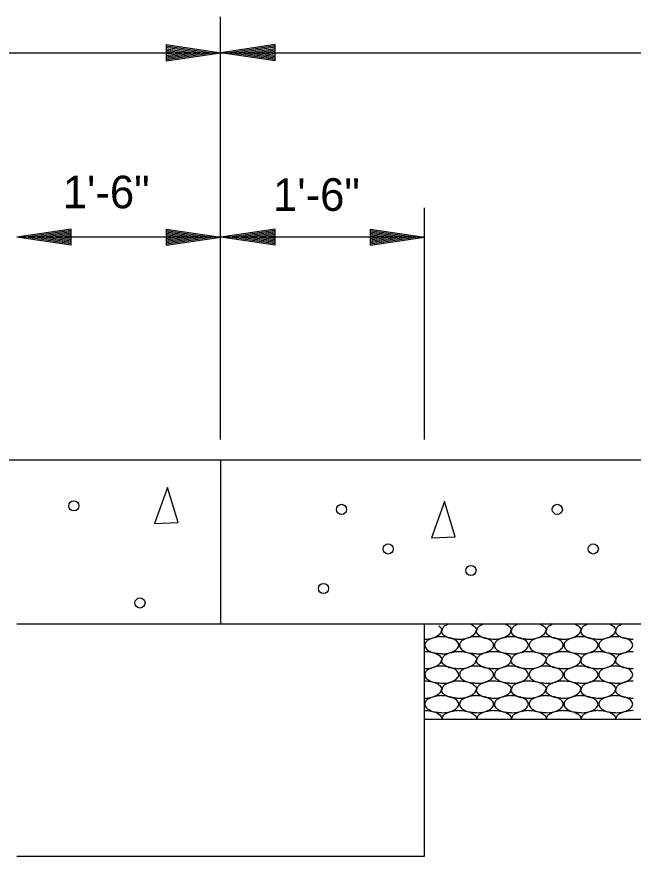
# Model space of a CAD drawing. Extents: x 3287 to 1767681, y -265 to 581440.
# Drawn here: x 3441.9 to 3464.58, y -239.71 to -208.81 of the extents above; entities that cross this region are included whole.
import ezdxf

# ---------------------------------------------------------------- set-up
doc = ezdxf.new("R2010")
doc.units = 0
doc.layers.add('Default', color=7, linetype='Continuous')

msp = doc.modelspace()

# ---------------------------------------------------------------- linework, layer by layer
at = {"layer": 'Default'}
for p, q in [((3449.399, -224.366), (3449.399, -208.806)), ((3447.401, -209.83), (3449.401, -210.13)), ((3447.401, -209.83), (3447.401, -210.43)), ((3447.401, -209.88), (3449.066, -210.13)), ((3447.401, -209.93), (3448.721, -210.13)), ((3447.401, -209.98), (3448.391, -210.13)), ((3447.401, -210.03), (3448.051, -210.13)), ((3447.401, -210.08), (3447.716, -210.13)), ((3451.401, -209.83), (3449.401, -210.13)), ((3451.401, -209.88), (3449.736, -210.13)), ((3451.401, -209.93), (3450.076, -210.13)), ((3451.401, -209.98), (3450.411, -210.13)), ((3451.401, -210.03), (3450.751, -210.13)), ((3451.401, -210.08), (3451.086, -210.13)), ((3451.401, -210.43), (3451.401, -209.83)), ((3349.405, -210.128), (3449.399, -210.128)), ((3447.401, -210.43), (3449.401, -210.13)), ((3447.401, -210.225), (3448.051, -210.13)), ((3447.401, -210.33), (3448.721, -210.13)), ((3447.401, -210.38), (3449.066, -210.13)), ((3447.401, -210.28), (3448.391, -210.13)), ((3447.401, -210.175), (3447.716, -210.13)), ((3449.399, -210.128), (3531.893, -210.128)), ((3451.401, -210.43), (3449.401, -210.13)), ((3451.401, -210.38), (3449.736, -210.13)), ((3451.401, -210.33), (3450.076, -210.13)), ((3451.401, -210.28), (3450.411, -210.13)), ((3451.401, -210.225), (3450.751, -210.13)), ((3451.401, -210.175), (3451.086, -210.13)), ((3456.898, -224.366), (3456.898, -215.841)), ((3449.399, -216.918), (3441.899, -216.918)), ((3443.902, -216.619), (3441.902, -216.919)), ((3443.902, -217.219), (3441.902, -216.919)), ((3443.902, -216.669), (3442.237, -216.919)), ((3443.902, -217.169), (3442.237, -216.919)), ((3443.902, -216.719), (3442.577, -216.919)), ((3443.902, -217.119), (3442.577, -216.919)), ((3443.902, -216.769), (3442.912, -216.919)), ((3443.902, -217.069), (3442.912, -216.919)), ((3443.902, -216.819), (3443.252, -216.919)), ((3443.902, -217.014), (3443.252, -216.919)), ((3443.902, -216.869), (3443.587, -216.919)), ((3443.902, -216.964), (3443.587, -216.919)), ((3443.902, -217.219), (3443.902, -216.619)), ((3447.401, -216.619), (3449.401, -216.919)), ((3447.401, -216.619), (3447.401, -217.219)), ((3447.401, -216.669), (3449.066, -216.919)), ((3447.401, -216.719), (3448.721, -216.919)), ((3447.401, -216.769), (3448.391, -216.919)), ((3447.401, -216.819), (3448.051, -216.919)), ((3447.401, -216.869), (3447.716, -216.919)), ((3447.401, -217.219), (3449.401, -216.919)), ((3447.401, -217.014), (3448.051, -216.919)), ((3447.401, -217.119), (3448.721, -216.919)), ((3447.401, -217.169), (3449.066, -216.919)), ((3447.401, -217.069), (3448.391, -216.919)), ((3447.401, -216.964), (3447.716, -216.919)), ((3456.898, -216.918), (3449.399, -216.918)), ((3451.401, -216.619), (3449.401, -216.919)), ((3451.401, -217.219), (3449.401, -216.919)), ((3451.401, -216.669), (3449.736, -216.919)), ((3451.401, -217.169), (3449.736, -216.919)), ((3451.401, -216.719), (3450.076, -216.919)), ((3451.401, -217.119), (3450.076, -216.919)), ((3451.401, -216.769), (3450.411, -216.919)), ((3451.401, -217.069), (3450.411, -216.919)), ((3451.401, -216.819), (3450.751, -216.919)), ((3451.401, -217.014), (3450.751, -216.919)), ((3451.401, -216.869), (3451.086, -216.919)), ((3451.401, -216.964), (3451.086, -216.919)), ((3451.401, -217.219), (3451.401, -216.619)), ((3454.901, -216.619), (3456.901, -216.919)), ((3454.901, -216.619), (3454.901, -217.219)), ((3454.901, -216.669), (3456.566, -216.919)), ((3454.901, -216.719), (3456.221, -216.919)), ((3454.901, -216.769), (3455.891, -216.919)), ((3454.901, -216.819), (3455.551, -216.919)), ((3454.901, -216.869), (3455.216, -216.919)), ((3454.901, -217.219), (3456.901, -216.919)), ((3454.901, -217.014), (3455.551, -216.919)), ((3454.901, -217.119), (3456.221, -216.919)), ((3454.901, -217.169), (3456.566, -216.919)), ((3454.901, -217.069), (3455.891, -216.919)), ((3454.901, -216.964), (3455.216, -216.919)), ((3349.405, -225.116), (3531.893, -225.116)), ((3449.399, -225.116), (3449.399, -231.157)), ((3441.899, -231.157), (3456.898, -231.157)), ((3456.898, -239.707), (3456.898, -231.157)), ((3456.898, -231.157), (3524.394, -231.157)), ((3456.898, -232.167), (3456.913, -232.167)), ((3458.178, -232.167), (3458.193, -232.167)), ((3459.458, -232.167), (3459.473, -232.167)), ((3460.738, -232.167), (3460.753, -232.167)), ((3462.018, -232.167), (3462.033, -232.167)), ((3463.298, -232.167), (3463.313, -232.167)), ((3456.898, -233.252), (3456.913, -233.252)), ((3458.178, -233.252), (3458.193, -233.252)), ((3459.458, -233.252), (3459.473, -233.252)), ((3460.738, -233.252), (3460.753, -233.252)), ((3462.018, -233.252), (3462.033, -233.252)), ((3463.298, -233.252), (3463.313, -233.252)), ((3456.898, -234.337), (3456.913, -234.337)), ((3458.178, -234.337), (3458.193, -234.337)), ((3459.458, -234.337), (3459.473, -234.337)), ((3460.738, -234.337), (3460.753, -234.337)), ((3462.018, -234.337), (3462.033, -234.337)), ((3463.298, -234.337), (3463.313, -234.337)), ((3456.898, -234.657), (3516.894, -234.657)), ((3441.899, -239.707), (3456.898, -239.707))]:
    msp.add_line(p, q, dxfattribs=at)
for points in [[(3447.446, -226.129), (3446.961, -227.454), (3447.841, -227.419), (3447.446, -226.129)], [(3457.636, -226.654), (3457.151, -227.984), (3458.031, -227.949), (3457.636, -226.654)]]:
    msp.add_lwpolyline(points, dxfattribs=at)
for centre in [(3443.998, -226.807), (3453.844, -226.94), (3461.785, -226.94), (3455.564, -228.396), (3463.109, -228.396), (3458.609, -229.191), (3453.182, -229.853), (3446.432, -230.383)]:
    msp.add_circle(centre, 0.187, dxfattribs=at)
for points in [[(3457.508, -231.402), (3457.508, -231.417), (3457.438, -231.552), (3457.363, -231.612), (3457.208, -231.682), (3456.993, -231.727), (3456.928, -231.728)], [(3457.432, -231.225), (3457.518, -231.322), (3457.538, -231.397), (3457.538, -231.402)], [(3457.728, -231.157), (3457.648, -231.167), (3457.538, -231.167), (3457.492, -231.164)], [(3458.178, -231.727), (3458.158, -231.727), (3457.993, -231.712), (3457.813, -231.682), (3457.678, -231.617), (3457.553, -231.502), (3457.533, -231.417), (3457.533, -231.402)], [(3457.553, -231.402), (3457.553, -231.397), (3457.593, -231.277), (3457.693, -231.197), (3457.779, -231.157)], [(3458.788, -231.402), (3458.788, -231.417), (3458.718, -231.552), (3458.643, -231.612), (3458.488, -231.682), (3458.273, -231.727), (3458.178, -231.727)], [(3458.582, -231.157), (3458.668, -231.197), (3458.798, -231.322), (3458.818, -231.397), (3458.818, -231.402)], [(3459.008, -231.157), (3458.928, -231.167), (3458.818, -231.167), (3458.7, -231.157)], [(3459.458, -231.727), (3459.438, -231.727), (3459.273, -231.712), (3459.093, -231.682), (3458.958, -231.617), (3458.833, -231.502), (3458.813, -231.417), (3458.813, -231.402)], [(3458.833, -231.402), (3458.833, -231.397), (3458.873, -231.277), (3458.973, -231.197), (3459.059, -231.157)], [(3460.068, -231.402), (3460.068, -231.417), (3459.998, -231.552), (3459.923, -231.612), (3459.768, -231.682), (3459.553, -231.727), (3459.458, -231.727)], [(3459.862, -231.157), (3459.948, -231.197), (3460.078, -231.322), (3460.098, -231.397), (3460.098, -231.402)], [(3460.287, -231.157), (3460.208, -231.167), (3460.098, -231.167), (3459.98, -231.157)], [(3460.738, -231.727), (3460.718, -231.727), (3460.553, -231.712), (3460.373, -231.682), (3460.238, -231.617), (3460.113, -231.502), (3460.093, -231.417), (3460.093, -231.402)], [(3460.113, -231.402), (3460.113, -231.397), (3460.153, -231.277), (3460.253, -231.197), (3460.339, -231.157)], [(3461.348, -231.402), (3461.348, -231.417), (3461.278, -231.552), (3461.203, -231.612), (3461.048, -231.682), (3460.833, -231.727), (3460.738, -231.727)], [(3461.142, -231.157), (3461.228, -231.197), (3461.358, -231.322), (3461.378, -231.397), (3461.378, -231.402)], [(3461.567, -231.157), (3461.488, -231.167), (3461.378, -231.167), (3461.26, -231.157)], [(3462.018, -231.727), (3461.998, -231.727), (3461.833, -231.712), (3461.653, -231.682), (3461.518, -231.617), (3461.393, -231.502), (3461.373, -231.417), (3461.373, -231.402)], [(3461.393, -231.402), (3461.393, -231.397), (3461.433, -231.277), (3461.533, -231.197), (3461.619, -231.157)], [(3462.628, -231.402), (3462.628, -231.417), (3462.558, -231.552), (3462.483, -231.612), (3462.328, -231.682), (3462.113, -231.727), (3462.018, -231.727)], [(3462.422, -231.157), (3462.508, -231.197), (3462.638, -231.322), (3462.658, -231.397), (3462.658, -231.402)], [(3462.847, -231.157), (3462.768, -231.167), (3462.658, -231.167), (3462.54, -231.157)], [(3463.298, -231.727), (3463.278, -231.727), (3463.113, -231.712), (3462.933, -231.682), (3462.798, -231.617), (3462.673, -231.502), (3462.653, -231.417), (3462.653, -231.402)], [(3462.673, -231.402), (3462.673, -231.397), (3462.713, -231.277), (3462.813, -231.197), (3462.899, -231.157)], [(3463.908, -231.402), (3463.908, -231.417), (3463.838, -231.552), (3463.763, -231.612), (3463.608, -231.682), (3463.393, -231.727), (3463.298, -231.727)], [(3463.702, -231.157), (3463.788, -231.197), (3463.918, -231.322), (3463.938, -231.397), (3463.938, -231.402)], [(3464.127, -231.157), (3464.048, -231.167), (3463.938, -231.167), (3463.82, -231.157)], [(3464.578, -231.727), (3464.558, -231.727), (3464.393, -231.712), (3464.213, -231.682), (3464.078, -231.617), (3463.953, -231.502), (3463.933, -231.417), (3463.933, -231.402)], [(3463.953, -231.402), (3463.953, -231.397), (3463.993, -231.277), (3464.093, -231.197), (3464.179, -231.157)], [(3457.538, -231.627), (3457.758, -231.652), (3458.013, -231.742), (3458.143, -231.867), (3458.163, -231.942), (3458.093, -232.077), (3458.018, -232.137), (3457.863, -232.207), (3457.648, -232.252), (3457.538, -232.252), (3457.373, -232.237), (3457.193, -232.207), (3457.058, -232.142), (3456.933, -232.027), (3456.913, -231.942), (3456.953, -231.822), (3457.053, -231.742), (3457.153, -231.697), (3457.303, -231.652), (3457.398, -231.632), (3457.538, -231.627)], [(3458.818, -231.627), (3459.038, -231.652), (3459.293, -231.742), (3459.423, -231.867), (3459.443, -231.942), (3459.373, -232.077), (3459.298, -232.137), (3459.143, -232.207), (3458.928, -232.252), (3458.818, -232.252), (3458.653, -232.237), (3458.473, -232.207), (3458.338, -232.142), (3458.213, -232.027), (3458.193, -231.942), (3458.233, -231.822), (3458.333, -231.742), (3458.433, -231.697), (3458.583, -231.652), (3458.678, -231.632), (3458.818, -231.627)], [(3460.098, -231.627), (3460.318, -231.652), (3460.573, -231.742), (3460.703, -231.867), (3460.723, -231.942), (3460.653, -232.077), (3460.578, -232.137), (3460.423, -232.207), (3460.208, -232.252), (3460.098, -232.252), (3459.933, -232.237), (3459.753, -232.207), (3459.618, -232.142), (3459.493, -232.027), (3459.473, -231.942), (3459.513, -231.822), (3459.613, -231.742), (3459.713, -231.697), (3459.863, -231.652), (3459.958, -231.632), (3460.098, -231.627)], [(3461.378, -231.627), (3461.598, -231.652), (3461.853, -231.742), (3461.983, -231.867), (3462.003, -231.942), (3461.933, -232.077), (3461.858, -232.137), (3461.703, -232.207), (3461.488, -232.252), (3461.378, -232.252), (3461.213, -232.237), (3461.033, -232.207), (3460.898, -232.142), (3460.773, -232.027), (3460.753, -231.942), (3460.793, -231.822), (3460.893, -231.742), (3460.993, -231.697), (3461.143, -231.652), (3461.238, -231.632), (3461.378, -231.627)], [(3462.658, -231.627), (3462.878, -231.652), (3463.133, -231.742), (3463.263, -231.867), (3463.283, -231.942), (3463.213, -232.077), (3463.138, -232.137), (3462.983, -232.207), (3462.768, -232.252), (3462.658, -232.252), (3462.493, -232.237), (3462.313, -232.207), (3462.178, -232.142), (3462.053, -232.027), (3462.033, -231.942), (3462.073, -231.822), (3462.173, -231.742), (3462.273, -231.697), (3462.423, -231.652), (3462.518, -231.632), (3462.658, -231.627)], [(3463.938, -231.627), (3464.158, -231.652), (3464.413, -231.742), (3464.543, -231.867), (3464.563, -231.942), (3464.493, -232.077), (3464.418, -232.137), (3464.263, -232.207), (3464.048, -232.252), (3463.938, -232.252), (3463.773, -232.237), (3463.593, -232.207), (3463.458, -232.142), (3463.333, -232.027), (3463.313, -231.942), (3463.353, -231.822), (3463.453, -231.742), (3463.553, -231.697), (3463.703, -231.652), (3463.798, -231.632), (3463.938, -231.627)], [(3456.913, -232.167), (3457.133, -232.192), (3457.388, -232.282), (3457.518, -232.407), (3457.538, -232.482), (3457.538, -232.487)], [(3457.553, -232.487), (3457.553, -232.482), (3457.593, -232.362), (3457.693, -232.282), (3457.793, -232.237), (3457.943, -232.192), (3458.038, -232.172), (3458.178, -232.167)], [(3458.193, -232.167), (3458.413, -232.192), (3458.668, -232.282), (3458.798, -232.407), (3458.818, -232.482), (3458.818, -232.487)], [(3458.833, -232.487), (3458.833, -232.482), (3458.873, -232.362), (3458.973, -232.282), (3459.073, -232.237), (3459.223, -232.192), (3459.318, -232.172), (3459.458, -232.167)], [(3459.473, -232.167), (3459.693, -232.192), (3459.948, -232.282), (3460.078, -232.407), (3460.098, -232.482), (3460.098, -232.487)], [(3460.113, -232.487), (3460.113, -232.482), (3460.153, -232.362), (3460.253, -232.282), (3460.353, -232.237), (3460.503, -232.192), (3460.598, -232.172), (3460.738, -232.167)], [(3460.753, -232.167), (3460.973, -232.192), (3461.228, -232.282), (3461.358, -232.407), (3461.378, -232.482), (3461.378, -232.487)], [(3461.393, -232.487), (3461.393, -232.482), (3461.433, -232.362), (3461.533, -232.282), (3461.633, -232.237), (3461.783, -232.192), (3461.878, -232.172), (3462.018, -232.167)], [(3462.033, -232.167), (3462.253, -232.192), (3462.508, -232.282), (3462.638, -232.407), (3462.658, -232.482), (3462.658, -232.487)], [(3462.673, -232.487), (3462.673, -232.482), (3462.713, -232.362), (3462.813, -232.282), (3462.913, -232.237), (3463.063, -232.192), (3463.158, -232.172), (3463.298, -232.167)], [(3463.313, -232.167), (3463.533, -232.192), (3463.788, -232.282), (3463.918, -232.407), (3463.938, -232.482), (3463.938, -232.487)], [(3463.953, -232.487), (3463.953, -232.482), (3463.993, -232.362), (3464.093, -232.282), (3464.193, -232.237), (3464.343, -232.192), (3464.438, -232.172), (3464.578, -232.167)], [(3457.508, -232.487), (3457.508, -232.502), (3457.438, -232.637), (3457.363, -232.697), (3457.208, -232.767), (3456.993, -232.812), (3456.898, -232.812)], [(3458.178, -232.812), (3458.158, -232.812), (3457.993, -232.797), (3457.813, -232.767), (3457.678, -232.702), (3457.553, -232.587), (3457.533, -232.502), (3457.533, -232.487)], [(3458.788, -232.487), (3458.788, -232.502), (3458.718, -232.637), (3458.643, -232.697), (3458.488, -232.767), (3458.273, -232.812), (3458.178, -232.812)], [(3459.458, -232.812), (3459.438, -232.812), (3459.273, -232.797), (3459.093, -232.767), (3458.958, -232.702), (3458.833, -232.587), (3458.813, -232.502), (3458.813, -232.487)], [(3460.068, -232.487), (3460.068, -232.502), (3459.998, -232.637), (3459.923, -232.697), (3459.768, -232.767), (3459.553, -232.812), (3459.458, -232.812)], [(3460.738, -232.812), (3460.718, -232.812), (3460.553, -232.797), (3460.373, -232.767), (3460.238, -232.702), (3460.113, -232.587), (3460.093, -232.502), (3460.093, -232.487)], [(3461.348, -232.487), (3461.348, -232.502), (3461.278, -232.637), (3461.203, -232.697), (3461.048, -232.767), (3460.833, -232.812), (3460.738, -232.812)], [(3462.018, -232.812), (3461.998, -232.812), (3461.833, -232.797), (3461.653, -232.767), (3461.518, -232.702), (3461.393, -232.587), (3461.373, -232.502), (3461.373, -232.487)], [(3462.628, -232.487), (3462.628, -232.502), (3462.558, -232.637), (3462.483, -232.697), (3462.328, -232.767), (3462.113, -232.812), (3462.018, -232.812)], [(3463.298, -232.812), (3463.278, -232.812), (3463.113, -232.797), (3462.933, -232.767), (3462.798, -232.702), (3462.673, -232.587), (3462.653, -232.502), (3462.653, -232.487)], [(3463.908, -232.487), (3463.908, -232.502), (3463.838, -232.637), (3463.763, -232.697), (3463.608, -232.767), (3463.393, -232.812), (3463.298, -232.812)], [(3464.578, -232.812), (3464.558, -232.812), (3464.393, -232.797), (3464.213, -232.767), (3464.078, -232.702), (3463.953, -232.587), (3463.933, -232.502), (3463.933, -232.487)], [(3457.538, -232.712), (3457.758, -232.737), (3458.013, -232.827), (3458.143, -232.952), (3458.163, -233.027), (3458.093, -233.162), (3458.018, -233.222), (3457.863, -233.292), (3457.648, -233.337), (3457.538, -233.337), (3457.373, -233.322), (3457.193, -233.292), (3457.058, -233.227), (3456.933, -233.112), (3456.913, -233.027), (3456.953, -232.907), (3457.053, -232.827), (3457.153, -232.782), (3457.303, -232.737), (3457.398, -232.717), (3457.538, -232.712)], [(3458.818, -232.712), (3459.038, -232.737), (3459.293, -232.827), (3459.423, -232.952), (3459.443, -233.027), (3459.373, -233.162), (3459.298, -233.222), (3459.143, -233.292), (3458.928, -233.337), (3458.818, -233.337), (3458.653, -233.322), (3458.473, -233.292), (3458.338, -233.227), (3458.213, -233.112), (3458.193, -233.027), (3458.233, -232.907), (3458.333, -232.827), (3458.433, -232.782), (3458.583, -232.737), (3458.678, -232.717), (3458.818, -232.712)], [(3460.098, -232.712), (3460.318, -232.737), (3460.573, -232.827), (3460.703, -232.952), (3460.723, -233.027), (3460.653, -233.162), (3460.578, -233.222), (3460.423, -233.292), (3460.208, -233.337), (3460.098, -233.337), (3459.933, -233.322), (3459.753, -233.292), (3459.618, -233.227), (3459.493, -233.112), (3459.473, -233.027), (3459.513, -232.907), (3459.613, -232.827), (3459.713, -232.782), (3459.863, -232.737), (3459.958, -232.717), (3460.098, -232.712)], [(3461.378, -232.712), (3461.598, -232.737), (3461.853, -232.827), (3461.983, -232.952), (3462.003, -233.027), (3461.933, -233.162), (3461.858, -233.222), (3461.703, -233.292), (3461.488, -233.337), (3461.378, -233.337), (3461.213, -233.322), (3461.033, -233.292), (3460.898, -233.227), (3460.773, -233.112), (3460.753, -233.027), (3460.793, -232.907), (3460.893, -232.827), (3460.993, -232.782), (3461.143, -232.737), (3461.238, -232.717), (3461.378, -232.712)], [(3462.658, -232.712), (3462.878, -232.737), (3463.133, -232.827), (3463.263, -232.952), (3463.283, -233.027), (3463.213, -233.162), (3463.138, -233.222), (3462.983, -233.292), (3462.768, -233.337), (3462.658, -233.337), (3462.493, -233.322), (3462.313, -233.292), (3462.178, -233.227), (3462.053, -233.112), (3462.033, -233.027), (3462.073, -232.907), (3462.173, -232.827), (3462.273, -232.782), (3462.423, -232.737), (3462.518, -232.717), (3462.658, -232.712)], [(3463.938, -232.712), (3464.158, -232.737), (3464.413, -232.827), (3464.543, -232.952), (3464.563, -233.027), (3464.493, -233.162), (3464.418, -233.222), (3464.263, -233.292), (3464.048, -233.337), (3463.938, -233.337), (3463.773, -233.322), (3463.593, -233.292), (3463.458, -233.227), (3463.333, -233.112), (3463.313, -233.027), (3463.353, -232.907), (3463.453, -232.827), (3463.553, -232.782), (3463.703, -232.737), (3463.798, -232.717), (3463.938, -232.712)], [(3456.913, -233.252), (3457.133, -233.277), (3457.388, -233.367), (3457.518, -233.492), (3457.538, -233.567), (3457.538, -233.572)], [(3457.553, -233.572), (3457.553, -233.567), (3457.593, -233.447), (3457.693, -233.367), (3457.793, -233.322), (3457.943, -233.277), (3458.038, -233.257), (3458.178, -233.252)], [(3458.193, -233.252), (3458.413, -233.277), (3458.668, -233.367), (3458.798, -233.492), (3458.818, -233.567), (3458.818, -233.572)], [(3458.833, -233.572), (3458.833, -233.567), (3458.873, -233.447), (3458.973, -233.367), (3459.073, -233.322), (3459.223, -233.277), (3459.318, -233.257), (3459.458, -233.252)], [(3459.473, -233.252), (3459.693, -233.277), (3459.948, -233.367), (3460.078, -233.492), (3460.098, -233.567), (3460.098, -233.572)], [(3460.113, -233.572), (3460.113, -233.567), (3460.153, -233.447), (3460.253, -233.367), (3460.353, -233.322), (3460.503, -233.277), (3460.598, -233.257), (3460.738, -233.252)], [(3460.753, -233.252), (3460.973, -233.277), (3461.228, -233.367), (3461.358, -233.492), (3461.378, -233.567), (3461.378, -233.572)], [(3461.393, -233.572), (3461.393, -233.567), (3461.433, -233.447), (3461.533, -233.367), (3461.633, -233.322), (3461.783, -233.277), (3461.878, -233.257), (3462.018, -233.252)], [(3462.033, -233.252), (3462.253, -233.277), (3462.508, -233.367), (3462.638, -233.492), (3462.658, -233.567), (3462.658, -233.572)], [(3462.673, -233.572), (3462.673, -233.567), (3462.713, -233.447), (3462.813, -233.367), (3462.913, -233.322), (3463.063, -233.277), (3463.158, -233.257), (3463.298, -233.252)], [(3463.313, -233.252), (3463.533, -233.277), (3463.788, -233.367), (3463.918, -233.492), (3463.938, -233.567), (3463.938, -233.572)], [(3463.953, -233.572), (3463.953, -233.567), (3463.993, -233.447), (3464.093, -233.367), (3464.193, -233.322), (3464.343, -233.277), (3464.438, -233.257), (3464.578, -233.252)], [(3457.508, -233.572), (3457.508, -233.587), (3457.438, -233.722), (3457.363, -233.782), (3457.208, -233.852), (3456.993, -233.897), (3456.898, -233.897)], [(3458.178, -233.897), (3458.158, -233.897), (3457.993, -233.882), (3457.813, -233.852), (3457.678, -233.787), (3457.553, -233.672), (3457.533, -233.587), (3457.533, -233.572)], [(3458.788, -233.572), (3458.788, -233.587), (3458.718, -233.722), (3458.643, -233.782), (3458.488, -233.852), (3458.273, -233.897), (3458.178, -233.897)], [(3459.458, -233.897), (3459.438, -233.897), (3459.273, -233.882), (3459.093, -233.852), (3458.958, -233.787), (3458.833, -233.672), (3458.813, -233.587), (3458.813, -233.572)], [(3460.068, -233.572), (3460.068, -233.587), (3459.998, -233.722), (3459.923, -233.782), (3459.768, -233.852), (3459.553, -233.897), (3459.458, -233.897)], [(3460.738, -233.897), (3460.718, -233.897), (3460.553, -233.882), (3460.373, -233.852), (3460.238, -233.787), (3460.113, -233.672), (3460.093, -233.587), (3460.093, -233.572)], [(3461.348, -233.572), (3461.348, -233.587), (3461.278, -233.722), (3461.203, -233.782), (3461.048, -233.852), (3460.833, -233.897), (3460.738, -233.897)], [(3462.018, -233.897), (3461.998, -233.897), (3461.833, -233.882), (3461.653, -233.852), (3461.518, -233.787), (3461.393, -233.672), (3461.373, -233.587), (3461.373, -233.572)], [(3462.628, -233.572), (3462.628, -233.587), (3462.558, -233.722), (3462.483, -233.782), (3462.328, -233.852), (3462.113, -233.897), (3462.018, -233.897)], [(3463.298, -233.897), (3463.278, -233.897), (3463.113, -233.882), (3462.933, -233.852), (3462.798, -233.787), (3462.673, -233.672), (3462.653, -233.587), (3462.653, -233.572)], [(3463.908, -233.572), (3463.908, -233.587), (3463.838, -233.722), (3463.763, -233.782), (3463.608, -233.852), (3463.393, -233.897), (3463.298, -233.897)], [(3464.578, -233.897), (3464.558, -233.897), (3464.393, -233.882), (3464.213, -233.852), (3464.078, -233.787), (3463.953, -233.672), (3463.933, -233.587), (3463.933, -233.572)], [(3457.538, -233.797), (3457.758, -233.822), (3458.013, -233.912), (3458.143, -234.037), (3458.163, -234.112), (3458.093, -234.247), (3458.018, -234.307), (3457.863, -234.377), (3457.648, -234.422), (3457.538, -234.422), (3457.373, -234.407), (3457.193, -234.377), (3457.058, -234.312), (3456.933, -234.197), (3456.913, -234.112), (3456.953, -233.992), (3457.053, -233.912), (3457.153, -233.867), (3457.303, -233.822), (3457.398, -233.802), (3457.538, -233.797)], [(3458.818, -233.797), (3459.038, -233.822), (3459.293, -233.912), (3459.423, -234.037), (3459.443, -234.112), (3459.373, -234.247), (3459.298, -234.307), (3459.143, -234.377), (3458.928, -234.422), (3458.818, -234.422), (3458.653, -234.407), (3458.473, -234.377), (3458.338, -234.312), (3458.213, -234.197), (3458.193, -234.112), (3458.233, -233.992), (3458.333, -233.912), (3458.433, -233.867), (3458.583, -233.822), (3458.678, -233.802), (3458.818, -233.797)], [(3460.098, -233.797), (3460.318, -233.822), (3460.573, -233.912), (3460.703, -234.037), (3460.723, -234.112), (3460.653, -234.247), (3460.578, -234.307), (3460.423, -234.377), (3460.208, -234.422), (3460.098, -234.422), (3459.933, -234.407), (3459.753, -234.377), (3459.618, -234.312), (3459.493, -234.197), (3459.473, -234.112), (3459.513, -233.992), (3459.613, -233.912), (3459.713, -233.867), (3459.863, -233.822), (3459.958, -233.802), (3460.098, -233.797)], [(3461.378, -233.797), (3461.598, -233.822), (3461.853, -233.912), (3461.983, -234.037), (3462.003, -234.112), (3461.933, -234.247), (3461.858, -234.307), (3461.703, -234.377), (3461.488, -234.422), (3461.378, -234.422), (3461.213, -234.407), (3461.033, -234.377), (3460.898, -234.312), (3460.773, -234.197), (3460.753, -234.112), (3460.793, -233.992), (3460.893, -233.912), (3460.993, -233.867), (3461.143, -233.822), (3461.238, -233.802), (3461.378, -233.797)], [(3462.658, -233.797), (3462.878, -233.822), (3463.133, -233.912), (3463.263, -234.037), (3463.283, -234.112), (3463.213, -234.247), (3463.138, -234.307), (3462.983, -234.377), (3462.768, -234.422), (3462.658, -234.422), (3462.493, -234.407), (3462.313, -234.377), (3462.178, -234.312), (3462.053, -234.197), (3462.033, -234.112), (3462.073, -233.992), (3462.173, -233.912), (3462.273, -233.867), (3462.423, -233.822), (3462.518, -233.802), (3462.658, -233.797)], [(3463.938, -233.797), (3464.158, -233.822), (3464.413, -233.912), (3464.543, -234.037), (3464.563, -234.112), (3464.493, -234.247), (3464.418, -234.307), (3464.263, -234.377), (3464.048, -234.422), (3463.938, -234.422), (3463.773, -234.407), (3463.593, -234.377), (3463.458, -234.312), (3463.333, -234.197), (3463.313, -234.112), (3463.353, -233.992), (3463.453, -233.912), (3463.553, -233.867), (3463.703, -233.822), (3463.798, -233.802), (3463.938, -233.797)], [(3456.913, -234.337), (3457.133, -234.362), (3457.388, -234.452), (3457.518, -234.577), (3457.538, -234.652), (3457.538, -234.657)], [(3457.553, -234.657), (3457.553, -234.652), (3457.593, -234.532), (3457.693, -234.452), (3457.793, -234.407), (3457.943, -234.362), (3458.038, -234.342), (3458.178, -234.337)], [(3458.193, -234.337), (3458.413, -234.362), (3458.668, -234.452), (3458.798, -234.577), (3458.818, -234.652), (3458.818, -234.657)], [(3458.833, -234.657), (3458.833, -234.652), (3458.873, -234.532), (3458.973, -234.452), (3459.073, -234.407), (3459.223, -234.362), (3459.318, -234.342), (3459.458, -234.337)], [(3459.473, -234.337), (3459.693, -234.362), (3459.948, -234.452), (3460.078, -234.577), (3460.098, -234.652), (3460.098, -234.657)], [(3460.113, -234.657), (3460.113, -234.652), (3460.153, -234.532), (3460.253, -234.452), (3460.353, -234.407), (3460.503, -234.362), (3460.598, -234.342), (3460.738, -234.337)], [(3460.753, -234.337), (3460.973, -234.362), (3461.228, -234.452), (3461.358, -234.577), (3461.378, -234.652), (3461.378, -234.657)], [(3461.393, -234.657), (3461.393, -234.652), (3461.433, -234.532), (3461.533, -234.452), (3461.633, -234.407), (3461.783, -234.362), (3461.878, -234.342), (3462.018, -234.337)], [(3462.033, -234.337), (3462.253, -234.362), (3462.508, -234.452), (3462.638, -234.577), (3462.658, -234.652), (3462.658, -234.657)], [(3462.673, -234.657), (3462.673, -234.652), (3462.713, -234.532), (3462.813, -234.452), (3462.913, -234.407), (3463.063, -234.362), (3463.158, -234.342), (3463.298, -234.337)], [(3463.313, -234.337), (3463.533, -234.362), (3463.788, -234.452), (3463.918, -234.577), (3463.938, -234.652), (3463.938, -234.657)], [(3463.953, -234.657), (3463.953, -234.652), (3463.993, -234.532), (3464.093, -234.452), (3464.193, -234.407), (3464.343, -234.362), (3464.438, -234.342), (3464.578, -234.337)]]:
    msp.add_spline(points, degree=3, dxfattribs=at)

# ---------------------------------------------------------------- texts
for p in [(3443.592, -215.855), (3451.326, -215.95)]:
    msp.add_text('1\'-6"', height=1.2, dxfattribs=at).set_placement(p)

doc.saveas('drawing.dxf')
